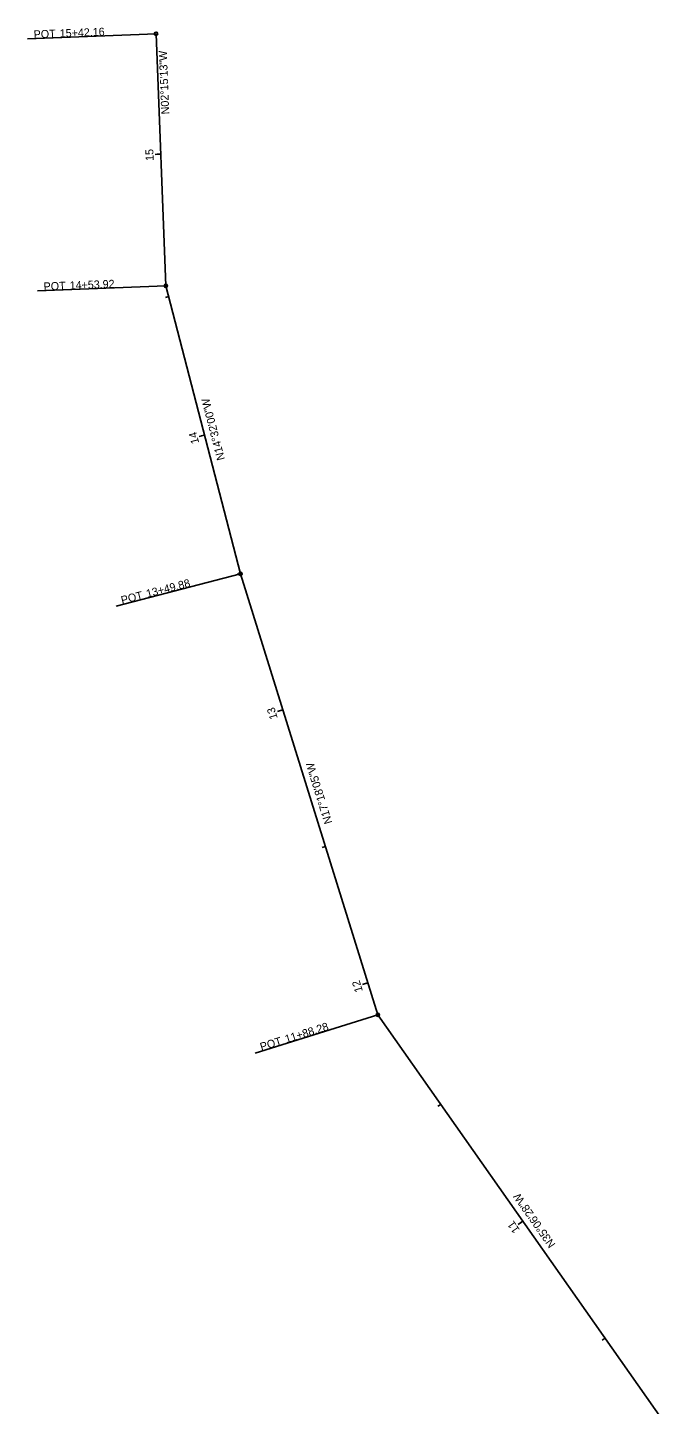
# Model space of a CAD drawing. Extents: x 2195310 to 2196150, y 661045 to 662024.
# Drawn here: x 2195309.8 to 2195535.5, y 661542.1 to 662023.7 of the extents above; entities that cross this region are included whole.
import ezdxf

# ---------------------------------------------------------------- set-up
doc = ezdxf.new("R2010")
doc.units = 0
for name, color, linetype in [('Default', 7, 'Continuous'), ('GE_X_Alignment', 7, 'Continuous'), ('GE_X_Alignment_1000_Stations', 7, 'Continuous'), ('GE_X_Alignment_100_Stations', 7, 'Continuous'), ('GE_X_Alignment_500_Stations', 7, 'Continuous')]:
    doc.layers.add(name, color=color, linetype=linetype)

msp = doc.modelspace()

# ---------------------------------------------------------------- linework, layer by layer
at = {"layer": 'Default'}
for centre in [(2195354.78, 662021.53), (2195354.78, 662021.53), (2195354.78, 662021.53), (2195356.44, 661979.4), (2195356.44, 661979.4), (2195356.52, 661977.44), (2195356.52, 661977.44), (2195356.52, 661977.44), (2195356.52, 661977.44), (2195356.52, 661977.44), (2195356.52, 661977.44), (2195358.25, 661933.35), (2195358.25, 661933.35), (2195358.25, 661933.35), (2195371.3, 661882.99), (2195371.3, 661882.99), (2195371.3, 661882.99), (2195371.3, 661882.99), (2195371.3, 661882.99), (2195371.3, 661882.99), (2195371.78, 661881.16), (2195384.36, 661832.64), (2195384.36, 661832.64), (2195384.36, 661832.64), (2195399.19, 661785.02), (2195408.39, 661755.5), (2195408.39, 661755.5), (2195408.39, 661755.5), (2195408.39, 661755.5), (2195408.39, 661755.5), (2195408.39, 661755.5), (2195428.93, 661689.54), (2195432.42, 661678.35), (2195432.42, 661678.35), (2195432.42, 661678.35), (2195483.19, 661606.13), (2195483.98, 661605.01), (2195483.98, 661605.01), (2195483.98, 661605.01), (2195483.98, 661605.01), (2195483.98, 661605.01), (2195483.98, 661605.01)]:
    msp.add_circle(centre, 0.0000833, dxfattribs=at)
at = {"layer": 'GE_X_Alignment'}
for p, q in [((2195358.25, 661933.35), (2195354.78, 662021.53)), ((2195384.36, 661832.64), (2195358.25, 661933.35)), ((2195432.42, 661678.35), (2195384.36, 661832.64)), ((2195535.54, 661531.67), (2195432.42, 661678.35))]:
    msp.add_line(p, q, dxfattribs=at)
at = {"layer": 'GE_X_Alignment_1000_Stations'}
for p, q in [((2195354.78, 662021.53), (2195309.82, 662019.76)), ((2195356.44, 661979.4), (2195355.24, 661979.35)), ((2195358.25, 661933.35), (2195313.29, 661931.58)), ((2195384.36, 661832.64), (2195340.8, 661821.35)), ((2195432.42, 661678.35), (2195389.45, 661664.97))]:
    msp.add_line(p, q, dxfattribs=at)
for centre in [(2195354.78, 662021.53), (2195358.25, 661933.35), (2195384.36, 661832.64), (2195432.42, 661678.35)]:
    msp.add_circle(centre, 0.6, dxfattribs=at)
at = {"layer": 'GE_X_Alignment_100_Stations'}
for p, q in [((2195354.78, 662021.53), (2195309.82, 662019.76)), ((2195356.44, 661979.4), (2195354.44, 661979.32)), ((2195358.25, 661933.35), (2195313.29, 661931.58)), ((2195359.23, 661929.56), (2195358.07, 661929.26)), ((2195371.78, 661881.16), (2195369.84, 661880.65)), ((2195384.36, 661832.64), (2195340.8, 661821.35)), ((2195384.33, 661832.76), (2195383.17, 661832.45)), ((2195399.19, 661785.02), (2195397.28, 661784.42)), ((2195414.06, 661737.28), (2195412.92, 661736.92)), ((2195428.93, 661689.54), (2195427.02, 661688.95)), ((2195432.42, 661678.35), (2195389.45, 661664.97)), ((2195454.43, 661647.04), (2195453.45, 661646.35)), ((2195483.19, 661606.13), (2195481.55, 661604.98)), ((2195511.95, 661565.23), (2195510.96, 661564.54))]:
    msp.add_line(p, q, dxfattribs=at)
for centre in [(2195354.78, 662021.53), (2195358.25, 661933.35), (2195384.36, 661832.64), (2195432.42, 661678.35)]:
    msp.add_circle(centre, 0.6, dxfattribs=at)
at = {"layer": 'GE_X_Alignment_500_Stations'}
for p, q in [((2195354.78, 662021.53), (2195309.82, 662019.76)), ((2195356.44, 661979.4), (2195354.44, 661979.32)), ((2195358.25, 661933.35), (2195313.29, 661931.58)), ((2195371.78, 661881.16), (2195370.62, 661880.86)), ((2195384.36, 661832.64), (2195340.8, 661821.35)), ((2195399.19, 661785.02), (2195398.05, 661784.66)), ((2195428.93, 661689.54), (2195427.79, 661689.18)), ((2195432.42, 661678.35), (2195389.45, 661664.97)), ((2195483.19, 661606.13), (2195482.21, 661605.44))]:
    msp.add_line(p, q, dxfattribs=at)
for centre in [(2195354.78, 662021.53), (2195358.25, 661933.35), (2195384.36, 661832.64), (2195432.42, 661678.35)]:
    msp.add_circle(centre, 0.6, dxfattribs=at)

# ---------------------------------------------------------------- texts
at = {"layer": 'GE_X_Alignment_1000_Stations'}
for s, rotation, p in [('POT', 2.2535, (2195312.02, 662019.89)), ('15+42.16', 2.2535, (2195321.14, 662020.25)), ('N02°15\'13"W', 92.2535, (2195359.43, 661993.38)), ('POT', 2.2535, (2195315.5, 661931.71)), ('14+53.92', 2.2535, (2195324.62, 661932.07)), ('N14°32\'00"W', 104.5333, (2195378.93, 661872.71)), ('13+49.88', 14.5333, (2195351.76, 661824.24)), ('POT', 14.5333, (2195342.93, 661821.95)), ('N17°18\'05"W', 107.3014, (2195416.5, 661745.6)), ('11+88.28', 17.3014, (2195400.4, 661668.43)), ('POT', 17.3014, (2195391.69, 661665.72)), ('N35°06\'28"W', 125.1079, (2195494.73, 661598.07))]:
    msp.add_text(s, height=2.8, rotation=rotation, dxfattribs=at).set_placement(p)
at = {"layer": 'GE_X_Alignment_100_Stations'}
for s, rotation, p in [('POT', 2.2535, (2195312.02, 662019.89)), ('15+42.16', 2.2535, (2195321.14, 662020.25)), ('N02°15\'13"W', 92.2535, (2195359.43, 661993.38)), ('15', 92.2535, (2195353.98, 661977.09)), ('POT', 2.2535, (2195315.5, 661931.71)), ('14+53.92', 2.2535, (2195324.62, 661932.07)), ('N14°32\'00"W', 104.5333, (2195378.93, 661872.71)), ('14', 104.5333, (2195369.9, 661878.45)), ('13+49.88', 14.5333, (2195351.76, 661824.24)), ('POT', 14.5333, (2195342.93, 661821.95)), ('13', 107.3014, (2195397.41, 661782.18)), ('N17°18\'05"W', 107.3014, (2195416.5, 661745.6)), ('12', 107.3014, (2195427.2, 661686.71)), ('11+88.28', 17.3014, (2195400.4, 661668.43)), ('POT', 17.3014, (2195391.69, 661665.72)), ('N35°06\'28"W', 125.1079, (2195494.73, 661598.07)), ('11', 125.1079, (2195482.23, 661603.16))]:
    msp.add_text(s, height=2.8, rotation=rotation, dxfattribs=at).set_placement(p)
at = {"layer": 'GE_X_Alignment_500_Stations'}
for s, rotation, p in [('POT', 2.2535, (2195312.02, 662019.89)), ('15+42.16', 2.2535, (2195321.14, 662020.25)), ('N02°15\'13"W', 92.2535, (2195359.43, 661993.38)), ('15', 92.2535, (2195353.98, 661977.09)), ('POT', 2.2535, (2195315.5, 661931.71)), ('14+53.92', 2.2535, (2195324.62, 661932.07)), ('N14°32\'00"W', 104.5333, (2195378.93, 661872.71)), ('13+49.88', 14.5333, (2195351.76, 661824.24)), ('POT', 14.5333, (2195342.93, 661821.95)), ('N17°18\'05"W', 107.3014, (2195416.5, 661745.6)), ('11+88.28', 17.3014, (2195400.4, 661668.43)), ('POT', 17.3014, (2195391.69, 661665.72)), ('N35°06\'28"W', 125.1079, (2195494.73, 661598.07))]:
    msp.add_text(s, height=2.8, rotation=rotation, dxfattribs=at).set_placement(p)

doc.saveas('drawing.dxf')
